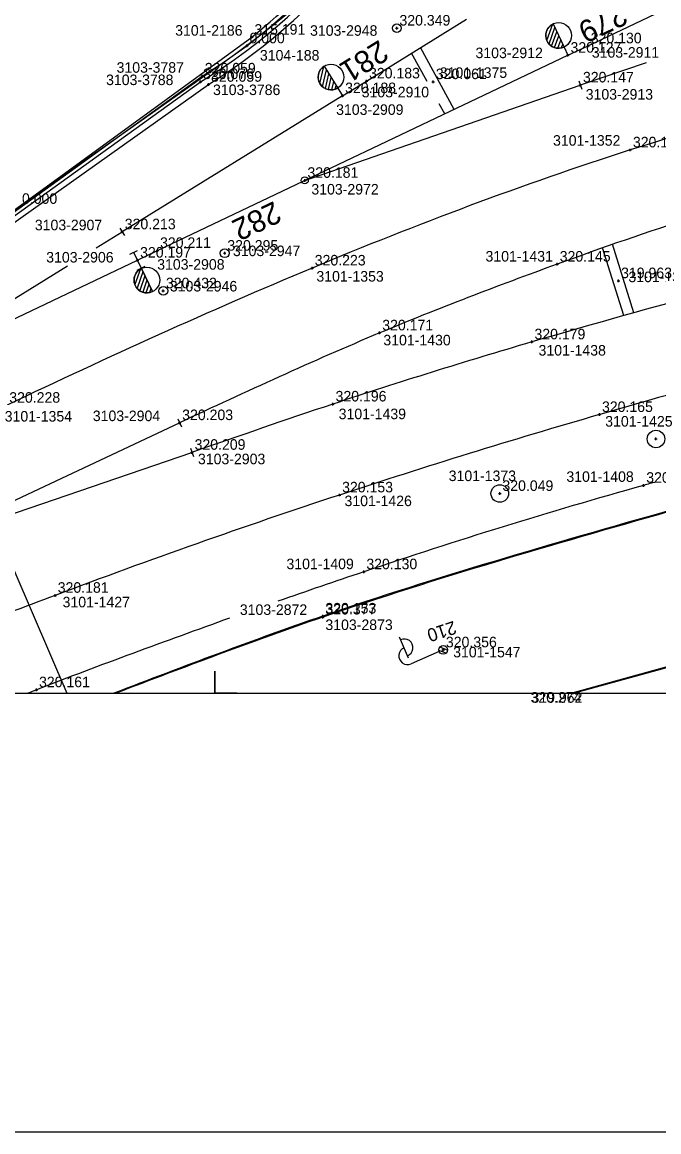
# Model space of a CAD drawing. Extents: x -821875 to -821475, y -1070280 to -1069975.
# Drawn here: x -821811 to -821774.7, y -1070275 to -1070211.8 of the extents above; entities that cross this region are included whole.
import ezdxf

# ---------------------------------------------------------------- set-up
doc = ezdxf.new("R2010")
doc.units = 0
for name, color, linetype in [('Vrstva 1', 7, 'Continuous'), ('Vrstva 11', 7, 'Continuous'), ('Vrstva 13', 7, 'Continuous'), ('Vrstva 14', 7, 'Continuous'), ('Vrstva 17', 7, 'Continuous'), ('Vrstva 2', 7, 'Continuous'), ('Vrstva 25', 7, 'Continuous'), ('Vrstva 28', 7, 'Continuous'), ('Vrstva 3', 7, 'Continuous'), ('Vrstva 43', 7, 'Continuous'), ('Vrstva 53', 7, 'Continuous'), ('Vrstva 60', 7, 'Continuous'), ('Vrstva 61', 7, 'Continuous'), ('Vrstva 7', 7, 'Continuous')]:
    doc.layers.add(name, color=color, linetype=linetype)

# ---------------------------------------------------------------- blocks, each defined once
blk = doc.blocks.new('BOD')
at = {"layer": 'Vrstva 3'}
for p, q in [((-0.15, 0), (0.15, 0)), ((0, -0.15), (0, 0.15))]:
    blk.add_line(p, q, dxfattribs=at)

msp = doc.modelspace()

# ---------------------------------------------------------------- linework, layer by layer
at = {"layer": 'Vrstva 1'}
msp.add_line((-821775.424, -1070214.071), (-821779.184, -1070215.339), dxfattribs=at)
for points in [[(-821475, -1069975), (-821875, -1069975), (-821875, -1070275), (-821475, -1070275)], [(-821500, -1070000), (-821850, -1070000), (-821850, -1070250), (-821500, -1070250)], [(-821500, -1070000), (-821850, -1070000), (-821850, -1070250), (-821500, -1070250)]]:
    msp.add_lwpolyline(points, close=True, dxfattribs=at)
for points in [[(-821792.73, -1070215.95), (-821805.285, -1070223.709)], [(-821800, -1070250), (-821800, -1070248.75), (-821800, -1070250)], [(-821801.25, -1070250), (-821800, -1070250)], [(-821800, -1070250), (-821798.75, -1070250), (-821800, -1070250)]]:
    msp.add_lwpolyline(points, dxfattribs=at)
for points in [[(-821710.276, -1070200.761), (-821741.264, -1070209.238), (-821760.235, -1070214.402), (-821776.338, -1070219.041), (-821794.464, -1070225.772), (-821811.866, -1070233.595), (-821823.5, -1070239.204)], [(-821768.767, -1070221.652), (-821772.719, -1070222.87), (-821780.508, -1070225.552), (-821790.618, -1070229.47), (-821802.014, -1070234.586)], [(-821758.62, -1070223.618), (-821771.612, -1070227.076), (-821781.946, -1070229.982), (-821793.276, -1070233.523), (-821801.308, -1070236.276)], [(-821772.109, -1070232.413), (-821778.099, -1070234.122), (-821792.905, -1070238.705), (-821809.105, -1070244.426), (-821819.525, -1070248.451)], [(-821774.873, -1070237.961), (-821775.577, -1070238.157), (-821791.523, -1070243.086), (-821796.42, -1070244.761)], [(-821799.16, -1070245.722), (-821810.17, -1070249.811), (-821810.654, -1070250)]]:
    msp.add_spline(points, degree=3, dxfattribs=at)
at = {"layer": 'Vrstva 11'}
msp.add_line((-821815.575, -1070233.423), (-821808.434, -1070250), dxfattribs=at)
at = {"layer": 'Vrstva 13'}
for points in [[(-821817.654, -1070226.97), (-821797.899, -1070212.619)], [(-821817.602, -1070227.017), (-821800.724, -1070214.827)], [(-821816.712, -1070226.921), (-821800.369, -1070215.3)]]:
    msp.add_lwpolyline(points, dxfattribs=at)
for centre, radius, start, end in [((-821818.298, -1070186.575), 33.273, 301.88355, 343.73085), ((-821818.089, -1070186.736), 33.615, 301.81377, 343.05221)]:
    msp.add_arc(centre, radius, start, end, dxfattribs=at)
msp.add_spline([(-821797.899, -1070212.619), (-821792.547, -1070207.633), (-821788.936, -1070202.321), (-821786.426, -1070195.852)], degree=3, dxfattribs=at)
at = {"layer": 'Vrstva 14'}
for p, q in [((-821755.35, -1070243.283), (-821779.667, -1070250)), ((-821779.579, -1070250), (-821755.252, -1070243.318))]:
    msp.add_line(p, q, dxfattribs=at)
for points in [[(-821774.103, -1070239.592), (-821793.856, -1070245.607), (-821805.756, -1070250)], [(-821774.135, -1070239.651), (-821793.856, -1070245.665), (-821805.638, -1070250)]]:
    msp.add_spline(points, degree=3, dxfattribs=at)
at = {"layer": 'Vrstva 17'}
msp.add_lwpolyline([(-821817.195, -1070226.928), (-821800.825, -1070215.148)], dxfattribs=at)
msp.add_arc((-821817.672, -1070187.259), 32.583, 301.1344, 344.40176, dxfattribs=at)
at = {"layer": 'Vrstva 2'}
for p, q in [((-821781.092, -1070212.8), (-821780.748, -1070211.857)), ((-821780.73, -1070211.847), (-821780.113, -1070213.174)), ((-821780.73, -1070211.847), (-821780.73, -1070211.847)), ((-821780.729, -1070211.852), (-821780.111, -1070213.179)), ((-821781.144, -1070212.402), (-821781.042, -1070212.125)), ((-821780.967, -1070212.998), (-821780.627, -1070212.067)), ((-821780.817, -1070213.125), (-821780.517, -1070212.304)), ((-821780.649, -1070213.204), (-821780.407, -1070212.542)), ((-821780.465, -1070213.239), (-821780.297, -1070212.779)), ((-821780.262, -1070213.223), (-821780.186, -1070213.016)), ((-821780.111, -1070213.179), (-821779.893, -1070213.645)), ((-821794.02, -1070215.252), (-821793.79, -1070214.275)), ((-821793.873, -1070215.434), (-821793.645, -1070214.469)), ((-821793.773, -1070214.263), (-821793.004, -1070215.509)), ((-821793.773, -1070214.264), (-821793.773, -1070214.263)), ((-821793.771, -1070214.268), (-821793.002, -1070215.513)), ((-821794.118, -1070214.863), (-821794.05, -1070214.576)), ((-821793.709, -1070215.543), (-821793.508, -1070214.692)), ((-821793.533, -1070215.602), (-821793.371, -1070214.915)), ((-821793.345, -1070215.615), (-821793.233, -1070215.137)), ((-821779.266, -1070215.103), (-821779.102, -1070215.575)), ((-821793.146, -1070215.575), (-821793.095, -1070215.36)), ((-821793.002, -1070215.513), (-821792.73, -1070215.95)), ((-821805.416, -1070223.497), (-821805.154, -1070223.921)), ((-821804.24, -1070225.816), (-821804.558, -1070226.711)), ((-821804.191, -1070225.788), (-821804.413, -1070225.324)), ((-821804.191, -1070225.788), (-821804.19, -1070225.788)), ((-821803.562, -1070227.11), (-821804.191, -1070225.788)), ((-821804.19, -1070225.788), (-821803.562, -1070227.11)), ((-821804.099, -1070225.98), (-821804.434, -1070226.922)), ((-821803.985, -1070226.219), (-821804.282, -1070227.056)), ((-821803.872, -1070226.459), (-821804.113, -1070227.14)), ((-821803.758, -1070226.699), (-821803.928, -1070227.177)), ((-821803.644, -1070226.938), (-821803.723, -1070227.163)), ((-821802.121, -1070234.36), (-821801.907, -1070234.812)), ((-821801.389, -1070236.039), (-821801.227, -1070236.513))]:
    msp.add_line(p, q, dxfattribs=at)
for points in [[(-821779.893, -1070213.645), (-821778.741, -1070213.109), (-821755.359, -1070201.967)], [(-821792.73, -1070215.95), (-821791.371, -1070215.11), (-821785.674, -1070211.591)], [(-821804.413, -1070225.324), (-821803.277, -1070224.772), (-821779.893, -1070213.645)], [(-821794.879, -1070220.776), (-821779.184, -1070215.339)], [(-821806.756, -1070224.621), (-821805.285, -1070223.709)], [(-821828.949, -1070236.999), (-821804.413, -1070225.324)], [(-821819.394, -1070232.452), (-821808.397, -1070225.637)], [(-821826.581, -1070246.124), (-821825.441, -1070245.619), (-821802.014, -1070234.586)], [(-821816.986, -1070241.637), (-821801.308, -1070236.276)]]:
    msp.add_lwpolyline(points, dxfattribs=at)
for centre, radius in [((-821780.421, -1070212.512), 0.731), ((-821793.388, -1070214.887), 0.731), ((-821794.879, -1070220.776), 0.2), ((-821803.875, -1070226.453), 0.731)]:
    msp.add_circle(centre, radius, dxfattribs=at)
for centre, start, end in [((-821780.421, -1070212.511), 114.96997, 294.93082), ((-821793.388, -1070214.886), 121.7355, 301.69635), ((-821803.876, -1070226.449), 115.46615, 295.427)]:
    msp.add_arc(centre, 0.732, start, end, dxfattribs=at)
at = {"layer": 'Vrstva 25'}
for p, q in [((-821788.965, -1070248.009), (-821789.482, -1070246.816)), ((-821786.743, -1070247.558), (-821787.188, -1070247.382)), ((-821787.22, -1070247.634), (-821788.826, -1070248.33)), ((-821786.829, -1070247.725), (-821787.238, -1070247.563))]:
    msp.add_line(p, q, dxfattribs=at)
msp.add_circle((-821786.991, -1070247.535), 0.25, dxfattribs=at)
msp.add_circle((-821786.991, -1070247.535), 0.25, dxfattribs=at)
for centre, start, end in [((-821789.025, -1070247.872), 113.43399, 293.43399), ((-821789.218, -1070247.41), 292.73141, 114.13656)]:
    msp.add_arc(centre, 0.5, start, end, dxfattribs=at)
at = {"layer": 'Vrstva 28'}
for p, q in [((-821789.663, -1070212.097), (-821789.613, -1070212.097)), ((-821799.468, -1070224.928), (-821799.418, -1070224.928)), ((-821802.965, -1070227.071), (-821802.915, -1070227.071))]:
    msp.add_line(p, q, dxfattribs=at)
for centre in [(-821789.638, -1070212.097), (-821799.443, -1070224.928), (-821802.94, -1070227.071)]:
    msp.add_circle(centre, 0.25, dxfattribs=at)
at = {"layer": 'Vrstva 3'}
for p, q in [((-821804.854, -1070224.98), (-821804.402, -1070224.765)), ((-821804.628, -1070224.872), (-821804.198, -1070225.776)), ((-821804.424, -1070225.883), (-821803.972, -1070225.668))]:
    msp.add_line(p, q, dxfattribs=at)
at = {"layer": 'Vrstva 43'}
for centre in [(-821774.875, -1070235.512), (-821783.772, -1070238.622)]:
    msp.add_circle(centre, 0.5, dxfattribs=at)
at = {"layer": 'Vrstva 53'}
msp.add_lwpolyline([(-821817.612, -1070227.046), (-821811.14, -1070222.26), (-821798.18, -1070213.11), (-821795.84, -1070211.25), (-821793.44, -1070208.9), (-821791.59, -1070206.8), (-821790.4, -1070205.13), (-821788.91, -1070202.52), (-821787.39, -1070199.35), (-821786.35, -1070195.94), (-821785.43, -1070192.45), (-821782.32, -1070181.25), (-821781.72, -1070179.14), (-821781.03, -1070177.19), (-821780.16, -1070174.72), (-821778.53, -1070171.61)], dxfattribs=at)
at = {"layer": 'Vrstva 7'}
for p, q in [((-821786.365, -1070216.724), (-821788.283, -1070213.203)), ((-821787.915, -1070215.131), (-821788.794, -1070213.518)), ((-821786.907, -1070216.983), (-821787.218, -1070216.412)), ((-821776.707, -1070228.475), (-821777.913, -1070224.616)), ((-821776.129, -1070228.313), (-821777.346, -1070224.416))]:
    msp.add_line(p, q, dxfattribs=at)

# ---------------------------------------------------------------- block references
at = {"layer": 'Vrstva 60', "xscale": 0.5, "yscale": 0.5}
for p in [(-821789.638, -1070212.097), (-821797.899, -1070212.619), (-821798.18, -1070213.11), (-821778.741, -1070213.109), (-821779.893, -1070213.645), (-821800.825, -1070215.148), (-821800.724, -1070214.827), (-821791.371, -1070215.11), (-821787.562, -1070215.153), (-821800.369, -1070215.3), (-821779.184, -1070215.339), (-821792.73, -1070215.95), (-821776.338, -1070219.041), (-821794.879, -1070220.776), (-821805.285, -1070223.709), (-821804.413, -1070225.324), (-821803.277, -1070224.772), (-821799.443, -1070224.928), (-821794.464, -1070225.772), (-821780.508, -1070225.552), (-821777.011, -1070226.495), (-821802.94, -1070227.071), (-821790.618, -1070229.47), (-821781.946, -1070229.982), (-821793.276, -1070233.523), (-821778.099, -1070234.122), (-821802.014, -1070234.586), (-821774.875, -1070235.512), (-821801.308, -1070236.276), (-821783.772, -1070238.622), (-821775.577, -1070238.157), (-821792.905, -1070238.705), (-821791.523, -1070243.086), (-821809.105, -1070244.426), (-821793.856, -1070245.607), (-821793.856, -1070245.665), (-821786.991, -1070247.535), (-821810.17, -1070249.811)]:
    msp.add_blockref('BOD', p, dxfattribs=at)

# ---------------------------------------------------------------- texts
at = {"layer": 'Vrstva 2'}
for s, rotation, p in [('279', 205.47875, (-821776.896, -1070210.661)), ('281', 211.70007, (-821790.634, -1070212.734)), ('282', 205.44689, (-821796.621, -1070221.932))]:
    msp.add_text(s, height=1.25, rotation=rotation, dxfattribs=at).set_placement(p)
at = {"layer": 'Vrstva 25'}
msp.add_text('210', height=0.75, rotation=198.18867, dxfattribs=at).set_placement((-821786.395, -1070245.869))
at = {"layer": 'Vrstva 60'}
for s, p in [('3101-2186', (-821802.263, -1070212.525)), ('3103-2948', (-821794.579, -1070212.531)), ('3103-2912', (-821785.154, -1070213.807)), ('3103-2911', (-821778.529, -1070213.779)), ('3104-188', (-821797.436, -1070213.944)), ('3103-3787', (-821805.601, -1070214.638)), ('3101-1375', (-821787.188, -1070214.932)), ('3103-3788', (-821806.199, -1070215.342)), ('3103-3786', (-821800.107, -1070215.91)), ('3103-2910', (-821791.637, -1070216.04)), ('3103-2913', (-821778.877, -1070216.168)), ('3103-2909', (-821793.093, -1070217.039)), ('3101-1352', (-821780.738, -1070218.796)), ('3103-2972', (-821794.505, -1070221.578)), ('3103-2907', (-821810.257, -1070223.616)), ('3103-2947', (-821798.973, -1070225.09)), ('3103-2906', (-821809.609, -1070225.454)), ('3103-2908', (-821803.287, -1070225.862)), ('3101-1431', (-821784.583, -1070225.399)), ('3101-1353', (-821794.218, -1070226.541)), ('3103-2946', (-821802.565, -1070227.105)), ('3101-1374', (-821776.443, -1070226.574)), ('3101-1430', (-821790.404, -1070230.176)), ('3101-1438', (-821781.563, -1070230.757)), ('3101-1354', (-821811.975, -1070234.519)), ('3103-2904', (-821806.954, -1070234.493)), ('3101-1439', (-821792.95, -1070234.383)), ('3101-1425', (-821777.764, -1070234.804)), ('3103-2903', (-821800.966, -1070236.95)), ('3101-1373', (-821786.682, -1070237.911)), ('3101-1408', (-821779.977, -1070237.958)), ('3101-1426', (-821792.616, -1070239.34)), ('3101-1409', (-821795.923, -1070242.933)), ('3101-1427', (-821808.677, -1070245.108)), ('3103-2872', (-821798.579, -1070245.54)), ('3103-2873', (-821793.706, -1070246.4)), ('3101-1547', (-821786.427, -1070247.959))]:
    msp.add_text(s, height=0.6, dxfattribs=at).set_placement(p)
at = {"layer": 'Vrstva 61'}
for s, p in [('320.349', (-821789.488, -1070211.947)), ('315.191', (-821797.749, -1070212.469)), ('0.000', (-821798.03, -1070212.96)), ('320.130', (-821778.591, -1070212.959)), ('320.127', (-821779.743, -1070213.495)), ('320.076', (-821800.675, -1070214.998)), ('320.059', (-821800.574, -1070214.677)), ('320.059', (-821800.219, -1070215.15)), ('320.183', (-821791.221, -1070214.96)), ('320.061', (-821787.412, -1070215.003)), ('320.147', (-821779.034, -1070215.189)), ('320.188', (-821792.58, -1070215.8)), ('320.194', (-821776.188, -1070218.891)), ('320.181', (-821794.729, -1070220.626)), ('0.000', (-821810.99, -1070222.11)), ('320.213', (-821805.135, -1070223.559)), ('320.211', (-821803.127, -1070224.622)), ('320.197', (-821804.263, -1070225.174)), ('320.295', (-821799.293, -1070224.778)), ('320.223', (-821794.314, -1070225.622)), ('320.145', (-821780.358, -1070225.402)), ('319.963', (-821776.861, -1070226.345)), ('320.432', (-821802.79, -1070226.921)), ('320.171', (-821790.468, -1070229.32)), ('320.179', (-821781.796, -1070229.832)), ('320.228', (-821811.716, -1070233.445)), ('320.196', (-821793.126, -1070233.373)), ('320.165', (-821777.949, -1070233.972)), ('320.203', (-821801.864, -1070234.436)), ('320.209', (-821801.158, -1070236.126)), ('320.153', (-821792.755, -1070238.555)), ('320.049', (-821783.622, -1070238.472)), ('320.097', (-821775.427, -1070238.007)), ('320.130', (-821791.373, -1070242.936)), ('320.181', (-821808.955, -1070244.276)), ('320.153', (-821793.706, -1070245.457)), ('320.377', (-821793.706, -1070245.515)), ('320.356', (-821786.841, -1070247.385)), ('320.161', (-821810.02, -1070249.661)), ('320.274', (-821782.019, -1070250.541)), ('319.962', (-821781.966, -1070250.547))]:
    msp.add_text(s, height=0.6, dxfattribs=at).set_placement(p)

doc.saveas('drawing.dxf')
